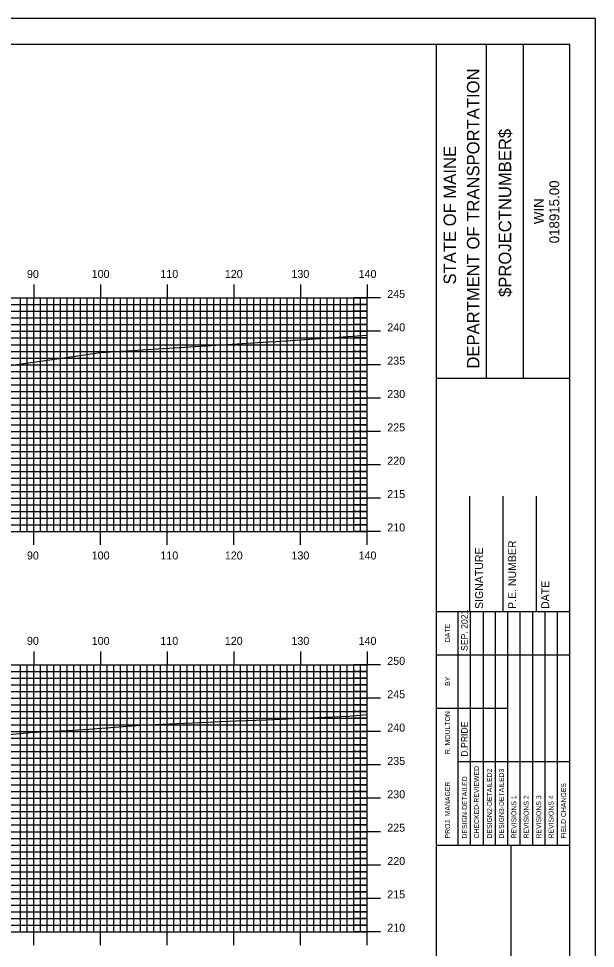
# Model space of a CAD drawing. Extents: x 1818457 to 1818800, y 442591 to 442811.
# Drawn here: x 1818710.4 to 1818796.9, y 442671.2 to 442810.5 of the extents above; entities that cross this region are included whole.
import ezdxf

# ---------------------------------------------------------------- set-up
doc = ezdxf.new("R2010")
doc.units = 0
for name, color, linetype in [('BORDER', 7, 'Continuous'), ('H_V ANNOTATION', 7, 'Continuous'), ('MAJOR', 7, 'Continuous'), ('MINOR', 7, 'Continuous'), ('PLOT BOUNDARY', 7, 'Continuous'), ('S_Roadway_Centerline', 7, 'Continuous')]:
    doc.layers.add(name, color=color, linetype=linetype)

msp = doc.modelspace()

# ---------------------------------------------------------------- linework, layer by layer
at = {"layer": 'BORDER'}
for p, q in [((1818773.04, 442596.67), (1818773.04, 442806.67)), ((1818780.5, 442756.66), (1818780.5, 442806.66)), ((1818786.09, 442756.66), (1818786.09, 442806.66)), ((1818773.04, 442756.65), (1818793.04, 442756.65)), ((1818778.04, 442721.67), (1818778.04, 442738.97)), ((1818783.04, 442721.67), (1818783.04, 442738.97)), ((1818788.04, 442721.67), (1818788.04, 442738.97)), ((1818773.04, 442721.67), (1818793.04, 442721.67)), ((1818773.04, 442686.67), (1818793.04, 442686.67)), ((1818784.22, 442616.67), (1818784.22, 442686.67))]:
    msp.add_line(p, q, dxfattribs=at)
msp.add_lwpolyline([(1818473.04, 442596.67), (1818793.04, 442596.67), (1818793.04, 442806.67), (1818473.04, 442806.67)], close=True, dxfattribs=at)
for points in [[(1818776.27, 442715.17), (1818776.27, 442721.67)], [(1818778.13, 442686.68), (1818778.13, 442721.67)], [(1818780, 442721.67), (1818780, 442686.68)], [(1818781.86, 442686.68), (1818781.86, 442721.67)], [(1818783.72, 442686.68), (1818783.72, 442721.67)], [(1818785.59, 442686.68), (1818785.59, 442721.67)], [(1818787.45, 442686.68), (1818787.45, 442721.67)], [(1818789.31, 442686.68), (1818789.31, 442721.67)], [(1818791.18, 442686.68), (1818791.18, 442721.67)], [(1818776.27, 442686.68), (1818776.27, 442720.26)], [(1818773.04, 442715.17), (1818793.04, 442715.17)], [(1818773.04, 442707.17), (1818776.27, 442707.17)], [(1818776.27, 442707.17), (1818783.72, 442707.17)], [(1818776.27, 442699.17), (1818793.04, 442699.17)]]:
    msp.add_lwpolyline(points, dxfattribs=at)
at = {"layer": 'MAJOR'}
for p, q in [((1818712.64, 442770.67), (1818712.64, 442768.67)), ((1818722.64, 442770.67), (1818722.64, 442768.67)), ((1818732.64, 442770.67), (1818732.64, 442768.67)), ((1818742.64, 442770.67), (1818742.64, 442768.67)), ((1818752.64, 442770.67), (1818752.64, 442768.67)), ((1818762.64, 442770.67), (1818762.64, 442768.67)), ((1818482.64, 442768.67), (1818762.64, 442768.67)), ((1818482.64, 442768.67), (1818762.64, 442768.67)), ((1818712.64, 442733.67), (1818712.64, 442768.67)), ((1818722.64, 442733.67), (1818722.64, 442768.67)), ((1818732.64, 442733.67), (1818732.64, 442768.67)), ((1818742.64, 442733.67), (1818742.64, 442768.67)), ((1818752.64, 442733.67), (1818752.64, 442768.67)), ((1818764.64, 442768.67), (1818760.63, 442768.67)), ((1818762.64, 442733.67), (1818762.64, 442768.67)), ((1818762.64, 442733.67), (1818762.64, 442768.67)), ((1818482.64, 442763.67), (1818762.64, 442763.67)), ((1818764.64, 442763.67), (1818760.63, 442763.67)), ((1818482.64, 442758.67), (1818762.64, 442758.67)), ((1818764.64, 442758.67), (1818760.63, 442758.67)), ((1818482.64, 442753.67), (1818762.64, 442753.67)), ((1818764.64, 442753.67), (1818760.63, 442753.67)), ((1818482.64, 442748.67), (1818762.64, 442748.67)), ((1818764.64, 442748.67), (1818760.63, 442748.67)), ((1818482.64, 442743.67), (1818762.64, 442743.67)), ((1818764.64, 442743.67), (1818760.63, 442743.67)), ((1818482.64, 442738.67), (1818762.64, 442738.67)), ((1818764.64, 442738.67), (1818760.63, 442738.67)), ((1818482.64, 442733.67), (1818762.64, 442733.67)), ((1818482.64, 442733.67), (1818762.64, 442733.67)), ((1818712.64, 442731.66), (1818712.64, 442733.67)), ((1818722.64, 442731.66), (1818722.64, 442733.67)), ((1818732.64, 442731.66), (1818732.64, 442733.67)), ((1818742.64, 442731.66), (1818742.64, 442733.67)), ((1818752.64, 442731.66), (1818752.64, 442733.67)), ((1818764.64, 442733.67), (1818760.63, 442733.67)), ((1818762.64, 442731.66), (1818762.64, 442733.67)), ((1818712.64, 442715.67), (1818712.64, 442713.67)), ((1818722.64, 442715.67), (1818722.64, 442713.67)), ((1818732.64, 442715.67), (1818732.64, 442713.67)), ((1818742.64, 442715.67), (1818742.64, 442713.67)), ((1818752.64, 442715.67), (1818752.64, 442713.67)), ((1818762.64, 442715.67), (1818762.64, 442713.67)), ((1818482.64, 442713.67), (1818762.64, 442713.67)), ((1818482.64, 442713.67), (1818762.64, 442713.67)), ((1818712.64, 442673.67), (1818712.64, 442713.67)), ((1818722.64, 442673.67), (1818722.64, 442713.67)), ((1818732.64, 442673.67), (1818732.64, 442713.67)), ((1818742.64, 442673.67), (1818742.64, 442713.67)), ((1818752.64, 442673.67), (1818752.64, 442713.67)), ((1818764.64, 442713.67), (1818760.63, 442713.67)), ((1818762.64, 442673.67), (1818762.64, 442713.67)), ((1818762.64, 442673.67), (1818762.64, 442713.67)), ((1818482.64, 442708.67), (1818762.64, 442708.67)), ((1818764.64, 442708.67), (1818760.63, 442708.67)), ((1818482.64, 442703.67), (1818762.64, 442703.67)), ((1818764.64, 442703.67), (1818760.63, 442703.67)), ((1818482.64, 442698.67), (1818762.64, 442698.67)), ((1818764.64, 442698.67), (1818760.63, 442698.67)), ((1818482.64, 442693.67), (1818762.64, 442693.67)), ((1818764.64, 442693.67), (1818760.63, 442693.67)), ((1818482.64, 442688.67), (1818762.64, 442688.67)), ((1818764.64, 442688.67), (1818760.63, 442688.67)), ((1818482.64, 442683.67), (1818762.64, 442683.67)), ((1818764.64, 442683.67), (1818760.63, 442683.67)), ((1818482.64, 442678.67), (1818762.64, 442678.67)), ((1818764.64, 442678.67), (1818760.63, 442678.67)), ((1818482.64, 442673.67), (1818762.64, 442673.67)), ((1818482.64, 442673.67), (1818762.64, 442673.67)), ((1818712.64, 442671.66), (1818712.64, 442673.67)), ((1818722.64, 442671.66), (1818722.64, 442673.67)), ((1818732.64, 442671.66), (1818732.64, 442673.67)), ((1818742.64, 442671.66), (1818742.64, 442673.67)), ((1818752.64, 442671.66), (1818752.64, 442673.67)), ((1818764.64, 442673.67), (1818760.63, 442673.67)), ((1818762.64, 442671.66), (1818762.64, 442673.67))]:
    msp.add_line(p, q, dxfattribs=at)
at = {"layer": 'MINOR'}
for p, q in [((1818710.64, 442733.67), (1818710.64, 442768.67)), ((1818711.64, 442733.67), (1818711.64, 442768.67)), ((1818713.64, 442733.67), (1818713.64, 442768.67)), ((1818714.64, 442733.67), (1818714.64, 442768.67)), ((1818715.64, 442733.67), (1818715.64, 442768.67)), ((1818716.64, 442733.67), (1818716.64, 442768.67)), ((1818717.64, 442733.67), (1818717.64, 442768.67)), ((1818718.64, 442733.67), (1818718.64, 442768.67)), ((1818719.64, 442733.67), (1818719.64, 442768.67)), ((1818720.64, 442733.67), (1818720.64, 442768.67)), ((1818721.64, 442733.67), (1818721.64, 442768.67)), ((1818723.64, 442733.67), (1818723.64, 442768.67)), ((1818724.64, 442733.67), (1818724.64, 442768.67)), ((1818725.64, 442733.67), (1818725.64, 442768.67)), ((1818726.64, 442733.67), (1818726.64, 442768.67)), ((1818727.64, 442733.67), (1818727.64, 442768.67)), ((1818728.64, 442733.67), (1818728.64, 442768.67)), ((1818729.64, 442733.67), (1818729.64, 442768.67)), ((1818730.64, 442733.67), (1818730.64, 442768.67)), ((1818731.64, 442733.67), (1818731.64, 442768.67)), ((1818733.64, 442733.67), (1818733.64, 442768.67)), ((1818734.64, 442733.67), (1818734.64, 442768.67)), ((1818735.64, 442733.67), (1818735.64, 442768.67)), ((1818736.64, 442733.67), (1818736.64, 442768.67)), ((1818737.64, 442733.67), (1818737.64, 442768.67)), ((1818738.64, 442733.67), (1818738.64, 442768.67)), ((1818739.64, 442733.67), (1818739.64, 442768.67)), ((1818740.64, 442733.67), (1818740.64, 442768.67)), ((1818741.64, 442733.67), (1818741.64, 442768.67)), ((1818743.64, 442733.67), (1818743.64, 442768.67)), ((1818744.64, 442733.67), (1818744.64, 442768.67)), ((1818745.64, 442733.67), (1818745.64, 442768.67)), ((1818746.64, 442733.67), (1818746.64, 442768.67)), ((1818747.64, 442733.67), (1818747.64, 442768.67)), ((1818748.64, 442733.67), (1818748.64, 442768.67)), ((1818749.64, 442733.67), (1818749.64, 442768.67)), ((1818750.64, 442733.67), (1818750.64, 442768.67)), ((1818751.64, 442733.67), (1818751.64, 442768.67)), ((1818753.64, 442733.67), (1818753.64, 442768.67)), ((1818754.64, 442733.67), (1818754.64, 442768.67)), ((1818755.64, 442733.67), (1818755.64, 442768.67)), ((1818756.64, 442733.67), (1818756.64, 442768.67)), ((1818757.64, 442733.67), (1818757.64, 442768.67)), ((1818758.64, 442733.67), (1818758.64, 442768.67)), ((1818759.64, 442733.67), (1818759.64, 442768.67)), ((1818760.64, 442733.67), (1818760.64, 442768.67)), ((1818761.64, 442733.67), (1818761.64, 442768.67)), ((1818482.64, 442767.67), (1818762.64, 442767.67)), ((1818762.64, 442767.67), (1818760.63, 442767.67)), ((1818482.64, 442766.67), (1818762.64, 442766.67)), ((1818762.64, 442766.67), (1818760.63, 442766.67)), ((1818482.64, 442765.67), (1818762.64, 442765.67)), ((1818482.64, 442764.67), (1818762.64, 442764.67)), ((1818762.64, 442765.67), (1818760.63, 442765.67)), ((1818762.64, 442764.67), (1818760.63, 442764.67)), ((1818482.64, 442762.67), (1818762.64, 442762.67)), ((1818482.64, 442761.67), (1818762.64, 442761.67)), ((1818762.64, 442762.67), (1818760.63, 442762.67)), ((1818762.64, 442761.67), (1818760.63, 442761.67)), ((1818482.64, 442760.67), (1818762.64, 442760.67)), ((1818762.64, 442760.67), (1818760.63, 442760.67)), ((1818482.64, 442759.67), (1818762.64, 442759.67)), ((1818762.64, 442759.67), (1818760.63, 442759.67)), ((1818482.64, 442757.67), (1818762.64, 442757.67)), ((1818762.64, 442757.67), (1818760.63, 442757.67)), ((1818482.64, 442756.67), (1818762.64, 442756.67)), ((1818762.64, 442756.67), (1818760.63, 442756.67)), ((1818482.64, 442755.67), (1818762.64, 442755.67)), ((1818482.64, 442754.67), (1818762.64, 442754.67)), ((1818762.64, 442755.67), (1818760.63, 442755.67)), ((1818762.64, 442754.67), (1818760.63, 442754.67)), ((1818482.64, 442752.67), (1818762.64, 442752.67)), ((1818762.64, 442752.67), (1818760.63, 442752.67)), ((1818482.64, 442751.67), (1818762.64, 442751.67)), ((1818482.64, 442750.67), (1818762.64, 442750.67)), ((1818762.64, 442751.67), (1818760.63, 442751.67)), ((1818762.64, 442750.67), (1818760.63, 442750.67)), ((1818482.64, 442749.67), (1818762.64, 442749.67)), ((1818762.64, 442749.67), (1818760.63, 442749.67)), ((1818482.64, 442747.67), (1818762.64, 442747.67)), ((1818762.64, 442747.67), (1818760.63, 442747.67)), ((1818482.64, 442746.67), (1818762.64, 442746.67)), ((1818762.64, 442746.67), (1818760.63, 442746.67)), ((1818482.64, 442745.67), (1818762.64, 442745.67)), ((1818762.64, 442745.67), (1818760.63, 442745.67)), ((1818482.64, 442744.67), (1818762.64, 442744.67)), ((1818762.64, 442744.67), (1818760.63, 442744.67)), ((1818482.64, 442742.67), (1818762.64, 442742.67)), ((1818762.64, 442742.67), (1818760.63, 442742.67)), ((1818482.64, 442741.67), (1818762.64, 442741.67)), ((1818762.64, 442741.67), (1818760.63, 442741.67)), ((1818482.64, 442740.67), (1818762.64, 442740.67)), ((1818482.64, 442739.67), (1818762.64, 442739.67)), ((1818762.64, 442740.67), (1818760.63, 442740.67)), ((1818762.64, 442739.67), (1818760.63, 442739.67)), ((1818482.64, 442737.67), (1818762.64, 442737.67)), ((1818482.64, 442736.67), (1818762.64, 442736.67)), ((1818762.64, 442737.67), (1818760.63, 442737.67)), ((1818762.64, 442736.67), (1818760.63, 442736.67)), ((1818482.64, 442735.67), (1818762.64, 442735.67)), ((1818762.64, 442735.67), (1818760.63, 442735.67)), ((1818482.64, 442734.67), (1818762.64, 442734.67)), ((1818762.64, 442734.67), (1818760.63, 442734.67)), ((1818710.64, 442673.67), (1818710.64, 442713.67)), ((1818711.64, 442673.67), (1818711.64, 442713.67)), ((1818713.64, 442673.67), (1818713.64, 442713.67)), ((1818714.64, 442673.67), (1818714.64, 442713.67)), ((1818715.64, 442673.67), (1818715.64, 442713.67)), ((1818716.64, 442673.67), (1818716.64, 442713.67)), ((1818717.64, 442673.67), (1818717.64, 442713.67)), ((1818718.64, 442673.67), (1818718.64, 442713.67)), ((1818719.64, 442673.67), (1818719.64, 442713.67)), ((1818720.64, 442673.67), (1818720.64, 442713.67)), ((1818721.64, 442673.67), (1818721.64, 442713.67)), ((1818723.64, 442673.67), (1818723.64, 442713.67)), ((1818724.64, 442673.67), (1818724.64, 442713.67)), ((1818725.64, 442673.67), (1818725.64, 442713.67)), ((1818726.64, 442673.67), (1818726.64, 442713.67)), ((1818727.64, 442673.67), (1818727.64, 442713.67)), ((1818728.64, 442673.67), (1818728.64, 442713.67)), ((1818729.64, 442673.67), (1818729.64, 442713.67)), ((1818730.64, 442673.67), (1818730.64, 442713.67)), ((1818731.64, 442673.67), (1818731.64, 442713.67)), ((1818733.64, 442673.67), (1818733.64, 442713.67)), ((1818734.64, 442673.67), (1818734.64, 442713.67)), ((1818735.64, 442673.67), (1818735.64, 442713.67)), ((1818736.64, 442673.67), (1818736.64, 442713.67)), ((1818737.64, 442673.67), (1818737.64, 442713.67)), ((1818738.64, 442673.67), (1818738.64, 442713.67)), ((1818739.64, 442673.67), (1818739.64, 442713.67)), ((1818740.64, 442673.67), (1818740.64, 442713.67)), ((1818741.64, 442673.67), (1818741.64, 442713.67)), ((1818743.64, 442673.67), (1818743.64, 442713.67)), ((1818744.64, 442673.67), (1818744.64, 442713.67)), ((1818745.64, 442673.67), (1818745.64, 442713.67)), ((1818746.64, 442673.67), (1818746.64, 442713.67)), ((1818747.64, 442673.67), (1818747.64, 442713.67)), ((1818748.64, 442673.67), (1818748.64, 442713.67)), ((1818749.64, 442673.67), (1818749.64, 442713.67)), ((1818750.64, 442673.67), (1818750.64, 442713.67)), ((1818751.64, 442673.67), (1818751.64, 442713.67)), ((1818753.64, 442673.67), (1818753.64, 442713.67)), ((1818754.64, 442673.67), (1818754.64, 442713.67)), ((1818755.64, 442673.67), (1818755.64, 442713.67)), ((1818756.64, 442673.67), (1818756.64, 442713.67)), ((1818757.64, 442673.67), (1818757.64, 442713.67)), ((1818758.64, 442673.67), (1818758.64, 442713.67)), ((1818759.64, 442673.67), (1818759.64, 442713.67)), ((1818760.64, 442673.67), (1818760.64, 442713.67)), ((1818761.64, 442673.67), (1818761.64, 442713.67)), ((1818482.64, 442712.67), (1818762.64, 442712.67)), ((1818482.64, 442711.67), (1818762.64, 442711.67)), ((1818762.64, 442712.67), (1818760.63, 442712.67)), ((1818762.64, 442711.67), (1818760.63, 442711.67)), ((1818482.64, 442710.67), (1818762.64, 442710.67)), ((1818762.64, 442710.67), (1818760.63, 442710.67)), ((1818482.64, 442709.67), (1818762.64, 442709.67)), ((1818762.64, 442709.67), (1818760.63, 442709.67)), ((1818482.64, 442707.67), (1818762.64, 442707.67)), ((1818762.64, 442707.67), (1818760.63, 442707.67)), ((1818482.64, 442706.67), (1818762.64, 442706.67)), ((1818762.64, 442706.67), (1818760.63, 442706.67)), ((1818482.64, 442705.67), (1818762.64, 442705.67)), ((1818482.64, 442704.67), (1818762.64, 442704.67)), ((1818762.64, 442705.67), (1818760.63, 442705.67)), ((1818762.64, 442704.67), (1818760.63, 442704.67)), ((1818482.64, 442702.67), (1818762.64, 442702.67)), ((1818482.64, 442701.67), (1818762.64, 442701.67)), ((1818762.64, 442702.67), (1818760.63, 442702.67)), ((1818762.64, 442701.67), (1818760.63, 442701.67)), ((1818482.64, 442700.67), (1818762.64, 442700.67)), ((1818762.64, 442700.67), (1818760.63, 442700.67)), ((1818482.64, 442699.67), (1818762.64, 442699.67)), ((1818762.64, 442699.67), (1818760.63, 442699.67)), ((1818482.64, 442697.67), (1818762.64, 442697.67)), ((1818762.64, 442697.67), (1818760.63, 442697.67)), ((1818482.64, 442696.67), (1818762.64, 442696.67)), ((1818762.64, 442696.67), (1818760.63, 442696.67)), ((1818482.64, 442695.67), (1818762.64, 442695.67)), ((1818762.64, 442695.67), (1818760.63, 442695.67)), ((1818482.64, 442694.67), (1818762.64, 442694.67)), ((1818762.64, 442694.67), (1818760.63, 442694.67)), ((1818482.64, 442692.67), (1818762.64, 442692.67)), ((1818762.64, 442692.67), (1818760.63, 442692.67)), ((1818482.64, 442691.67), (1818762.64, 442691.67)), ((1818482.64, 442690.67), (1818762.64, 442690.67)), ((1818762.64, 442691.67), (1818760.63, 442691.67)), ((1818762.64, 442690.67), (1818760.63, 442690.67)), ((1818482.64, 442689.67), (1818762.64, 442689.67)), ((1818762.64, 442689.67), (1818760.63, 442689.67)), ((1818482.64, 442687.67), (1818762.64, 442687.67)), ((1818482.64, 442686.67), (1818762.64, 442686.67)), ((1818762.64, 442687.67), (1818760.63, 442687.67)), ((1818762.64, 442686.67), (1818760.63, 442686.67)), ((1818482.64, 442685.67), (1818762.64, 442685.67)), ((1818762.64, 442685.67), (1818760.63, 442685.67)), ((1818482.64, 442684.67), (1818762.64, 442684.67)), ((1818762.64, 442684.67), (1818760.63, 442684.67)), ((1818482.64, 442682.67), (1818762.64, 442682.67)), ((1818762.64, 442682.67), (1818760.63, 442682.67)), ((1818482.64, 442681.67), (1818762.64, 442681.67)), ((1818762.64, 442681.67), (1818760.63, 442681.67)), ((1818482.64, 442680.67), (1818762.64, 442680.67)), ((1818482.64, 442679.67), (1818762.64, 442679.67)), ((1818762.64, 442680.67), (1818760.63, 442680.67)), ((1818762.64, 442679.67), (1818760.63, 442679.67)), ((1818482.64, 442677.67), (1818762.64, 442677.67)), ((1818482.64, 442676.67), (1818762.64, 442676.67)), ((1818762.64, 442677.67), (1818760.63, 442677.67)), ((1818762.64, 442676.67), (1818760.63, 442676.67)), ((1818482.64, 442675.67), (1818762.64, 442675.67)), ((1818762.64, 442675.67), (1818760.63, 442675.67)), ((1818482.64, 442674.67), (1818762.64, 442674.67)), ((1818762.64, 442674.67), (1818760.63, 442674.67))]:
    msp.add_line(p, q, dxfattribs=at)
at = {"layer": 'PLOT BOUNDARY'}
msp.add_lwpolyline([(1818456.85, 442590.55), (1818796.85, 442590.55), (1818796.85, 442810.55), (1818456.85, 442810.55)], close=True, dxfattribs=at)
at = {"layer": 'S_Roadway_Centerline'}
for points in [[(1818565.65, 442742.58), (1818580.46, 442744.22), (1818585.17, 442744.89), (1818596.16, 442745.95), (1818612.21, 442748.1), (1818613.05, 442748.17), (1818618.72, 442748.68), (1818628.62, 442749.49), (1818629.81, 442749.58), (1818633.22, 442749.81), (1818647.29, 442750.61), (1818656.97, 442752.19), (1818668.04, 442753.65), (1818681.71, 442755.35), (1818688.66, 442756.02), (1818698.19, 442757.04), (1818709.76, 442758.67), (1818715.73, 442759.51), (1818722.62, 442760.52), (1818747.81, 442762.07), (1818749, 442762.13), (1818762.64, 442763.07)], [(1818558.62, 442686.34), (1818592.64, 442689.86), (1818624.71, 442694.18), (1818626.66, 442694.46), (1818628.43, 442694.76), (1818643.28, 442696.68), (1818652.59, 442698.28), (1818659.99, 442699.02), (1818673.9, 442700.48), (1818677.73, 442700.87), (1818679.7, 442701.16), (1818687.16, 442701.55), (1818695.53, 442702.14), (1818698.53, 442702.3), (1818712.14, 442703.56), (1818720.25, 442703.99), (1818728.64, 442704.61), (1818742.98, 442705.29), (1818747.44, 442705.45), (1818752.79, 442705.66), (1818759.89, 442705.98), (1818762.64, 442706.21)]]:
    msp.add_lwpolyline(points, dxfattribs=at)

# ---------------------------------------------------------------- texts
at = {"layer": 'BORDER'}
for s, height, p in [('DEPARTMENT OF TRANSPORTATION', 1.8635, (1818779.45, 442758.08)), ('$PROJECTNUMBER$', 1.8635, (1818784.22, 442768.82)), ('STATE OF MAINE', 1.8635, (1818775.95, 442770.69)), ('018915.00', 1.491, (1818791.43, 442776.86)), ('WIN', 1.491, (1818789.11, 442779.73)), ('SIGNATURE', 1.181, (1818780, 442722.06)), ('P.E. NUMBER', 1.1811, (1818784.96, 442722.06)), ('DATE', 1.181, (1818789.92, 442722.06)), ('SEP. 2021', 0.969, (1818777.69, 442715.76)), ('DATE', 0.743, (1818775.05, 442717.08)), ('BY', 0.743, (1818775.05, 442710.54)), ('R. MOULTON', 0.745, (1818775.05, 442700.28)), ('D.PRIDE', 0.969, (1818777.69, 442699.92)), ('CHECKED-REVIEWED', 0.7455, (1818779.4, 442687.65)), ('DESIGN2-DETAILED2', 0.7455, (1818781.34, 442687.65)), ('DESIGN3-DETAILED3', 0.7455, (1818783.13, 442687.65)), ('DESIGN-DETAILED', 0.7455, (1818777.61, 442687.65)), ('PROJ. MANAGER', 0.7455, (1818775.05, 442687.65)), ('FIELD CHANGES', 0.7455, (1818792.44, 442687.65)), ('REVISIONS 1', 0.7455, (1818784.99, 442687.65)), ('REVISIONS 2', 0.7455, (1818786.85, 442687.65)), ('REVISIONS 3', 0.7455, (1818788.72, 442687.65)), ('REVISIONS 4', 0.7455, (1818790.58, 442687.65))]:
    msp.add_text(s, height=height, rotation=90, dxfattribs=at).set_placement(p)
at = {"layer": 'H_V ANNOTATION'}
for s, p in [('90', (1818711.61, 442771.67)), ('100', (1818721.32, 442771.67)), ('110', (1818731.62, 442771.67)), ('120', (1818741.28, 442771.67)), ('130', (1818751.27, 442771.67)), ('140', (1818761.34, 442771.67)), ('245', (1818765.64, 442768.67)), ('240', (1818765.64, 442763.67)), ('235', (1818765.64, 442758.67)), ('230', (1818765.64, 442753.67)), ('225', (1818765.64, 442748.67)), ('220', (1818765.64, 442743.67)), ('215', (1818765.64, 442738.67)), ('210', (1818765.64, 442733.67)), ('90', (1818711.61, 442729.47)), ('100', (1818721.32, 442729.47)), ('110', (1818731.62, 442729.47)), ('120', (1818741.28, 442729.47)), ('130', (1818751.27, 442729.47)), ('140', (1818761.34, 442729.47)), ('90', (1818711.61, 442716.67)), ('100', (1818721.32, 442716.67)), ('110', (1818731.62, 442716.67)), ('120', (1818741.28, 442716.67)), ('130', (1818751.27, 442716.67)), ('140', (1818761.34, 442716.67)), ('250', (1818765.64, 442713.67)), ('245', (1818765.64, 442708.67)), ('240', (1818765.64, 442703.67)), ('235', (1818765.64, 442698.67)), ('230', (1818765.64, 442693.67)), ('225', (1818765.64, 442688.67)), ('220', (1818765.64, 442683.67)), ('215', (1818765.64, 442678.67)), ('210', (1818765.64, 442673.67))]:
    msp.add_text(s, height=1.2, dxfattribs=at).set_placement(p)

doc.saveas('drawing.dxf')
